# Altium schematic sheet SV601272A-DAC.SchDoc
size 431 x 279 mm; Date: Not shown in title block; ApprovedBy: Not shown in title block; CheckedBy: Not shown in title block; Author: Not shown in title block; CompanyName: Not shown in title block; Engineer: Not shown in title block; Organization: Not shown in title block; Address1: Not shown in title block; Address2: Not shown in title block; Address3: Not shown in title block; Address4: Not shown in title block; DocumentNumber: 8; Revision: Use project parameter SCH_Rev; SheetNumber: 8; SheetTotal: 11; PageSetup: Record=PageOptions¦CenterHorizontal=True¦CenterVertical=True¦PrintScale=1.00¦XCorrection=1.00¦YCorrection=1.00¦PrintKind=0¦BorderSize=5000000¦LeftOffset=0¦BottomOffset=0¦Orientation=2¦PaperLength=1000¦PaperWidth=1000¦Scale=100¦PaperSource=15¦PrintQuality=600¦MediaType=1¦DitherType=10¦PaperKind=Letter¦PrintScaleMode=1
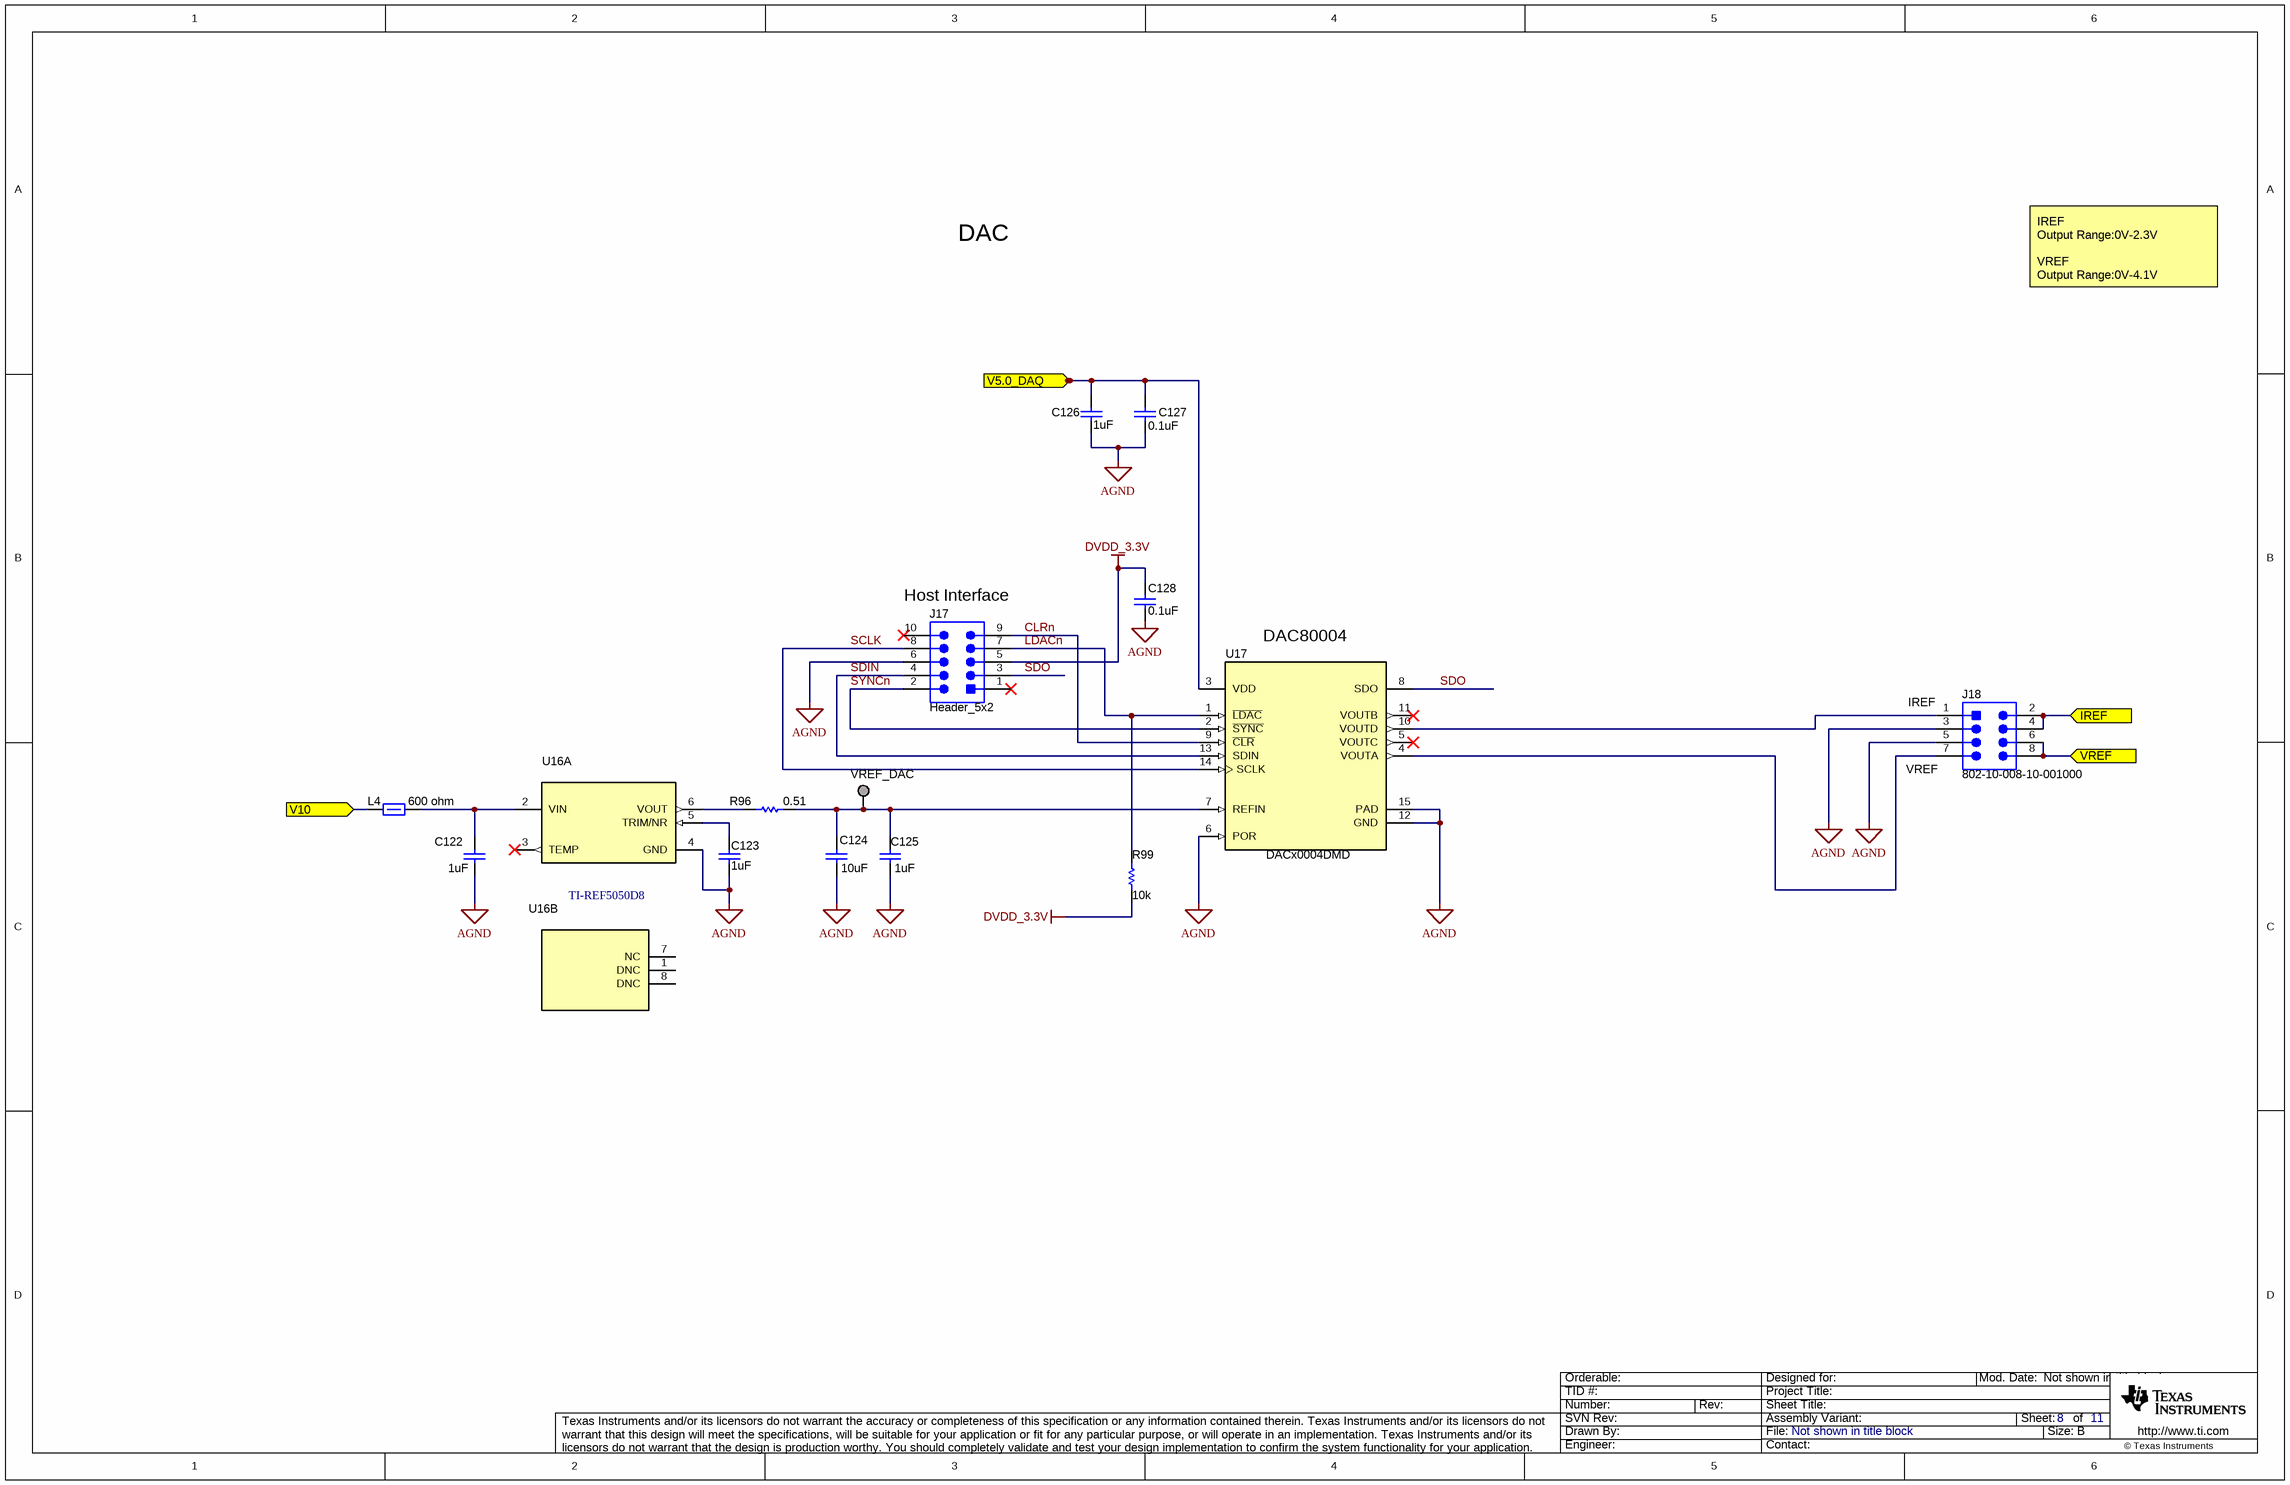
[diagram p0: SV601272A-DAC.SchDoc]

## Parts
C122  ValueDisplayed: 1uF  [1206]  (hidden comment: Capacitor)
C123  ValueDisplayed: 1uF  [1206]  (hidden comment: Capacitor)
C124  ValueDisplayed: 10uF  [0805_HV]  (hidden comment: Capacitor)
C125  ValueDisplayed: 1uF  [1206]  (hidden comment: Capacitor)
C126  ValueDisplayed: 1uF  [1206]  (hidden comment: Capacitor)
C127  ValueDisplayed: 0.1uF  [0603]  (hidden comment: Capacitor)
C128  ValueDisplayed: 0.1uF  [0603]  (hidden comment: Capacitor)
J17  Header_5x2  [Assman_AWHW-10G-0x02-T]
J18  802-10-008-10-001000  [Mill-Max_802-10-008-10-001000]
L4  value 600 ohm  [0603]  (hidden comment: Ferrite_Bead)
R96  ValueDisplayed: 0.51  [0603]  (hidden comment: Resistor)
R99  ValueDisplayed: 10k  [0603]  (hidden comment: Resistor)
U16  TI-REF5050D8  [D0008A_N]  (parts A,B of 2)
U17  DACx0004DMD  [DMD0014A]
VREF_DAC  Pogo Pad  [PogoPad]  (value not drawn)  (no BOM)

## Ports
IREF, V5.0_DAQ, V10, VREF

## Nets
AGND: C122.2 C123.2 C124.2 C125.2 C126.2 C127.2 C128.2 J17.6 J18.3 J18.5 U16.4(GND) U17.6(POR) U17.12(GND) U17.15(PAD)
DVDD_3.3V: C128.1 J17.5 R99.1
CLRn: J17.9 U17.9(~{CLR})
IREF: J18.2 J18.4 ; port IREF
LDACn: J17.7 R99.2 U17.1(~{LDAC})
SCLK: J17.8 U17.14(SCLK)
SDIN: J17.4 U17.13(SDIN)
SDO: J17.3 U17.8(SDO)
SYNCn: J17.2 U17.2(~{SYNC})
V5.0_DAQ: C126.1 C127.1 U17.3(VDD) ; port V5.0_DAQ
V10: L4.1 ; port V10
VREF: J18.6 J18.8 ; port VREF
NetC122_1: C122.1 L4.2 U16.2(VIN)
NetC123_1: C123.1 U16.5(TRIM/NR)
NetC124_1: C124.1 C125.1 R96.2 U17.7(REFIN) VREF_DAC.1
NetJ18_1: J18.1 U17.10(VOUTD)
NetJ18_7: J18.7 U17.4(VOUTA)
NetR96_1: R96.1 U16.6(VOUT)

Not connected (* = marked no-connect by the designer): J17 1* 10*; U16 1(DNC) 3(TEMP)* 7(NC) 8(DNC); U17 5(VOUTC)* 11(VOUTB)*

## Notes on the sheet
- DAC
- IREF
  Output Range:0V-2.3V
  VREF
  Output Range:0V-4.1V
- (near J17) Host Interface
- (near U17) DAC80004
- (near J18) IREF
- (near J18) VREF

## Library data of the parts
C122 C123 C125 C126 = CMP-0008509-2: CAP, CERM, 1 uF, 25 V, +/- 10%, X7R, 1206; PartNumber: 12063C105KAT2A; Manufacturer: AVX; Polarized: N; Value: 1uF; U/M: EA; Cap_F: 1µF; ESR_ohm: 0.013; Value1: 0.013 ohm; VDC_V: 25V; TaMin_C: -55°C; TaMax_C: 125°C; SizeArea_mm2: 5.12; SizeAreaWB_mm2: 10.92; SizeX_mm: 3.2; SizeY_mm: 1.6; SizeZ_mm: 1.35; AEC Category: Q200
C124 = CMP-0008273-1: CAP, CERM, 10 uF, 35 V, +/- 10%, X6S, 0805; PartNumber: GRM21BC8YA106KE11L; Manufacturer: MuRata; Polarized: N; Value: 10uF; U/M: EA; Cap_F: 10µF; Value1: Unknown; VDC_V: 35V; TaMin_C: -55°C; TaMax_C: 105°C; Cap_Case: 0805; SizeArea_mm2: 2.5; SizeAreaWB_mm2: 6.75; SizeX_mm: 2; SizeY_mm: 1.25; SizeZ_mm: 1.45; AEC Category: Q200
C127 C128 = CMP-0006857-4: CAP, CERM, 0.1 uF, 16 V, +/- 5%, X7R, 0603; PartNumber: C0603C104J4RACTU; Manufacturer: Kemet; Polarized: N; Value: 0.1uF; U/M: EA; Cap_F: 100nF; Value1: Unknown; VDC_V: 16V; TaMin_C: -55°C; TaMax_C: 125°C; SizeArea_mm2: 1.28; SizeAreaWB_mm2: 4.68; SizeX_mm: 1.6; SizeY_mm: 0.8; SizeZ_mm: 1; AEC Category: Q200
J17 = CMP-0075161-1: Header(Shrouded), 2.54mm, 5x2, Gold, TH; PartNumber: AWHW-10G-0202-T; Manufacturer: Assman WSW; Pitch_mm: 2.54; Gender: Male; Shrouded: Y; Row_Count: 2; CNHeader: False; Green_Lifecycle: Active; Green_REACh: Passed
J18 = CMP-0055096-1: Header, 2.54 mm, 4x2, Gold, TH; Manufacturer: Mill-Max; CNHeader: TRUE; Shrouded: N; Gender: Male; Row_Count: 2; RowSpacing_mm: 2.54; CT: FALSE
L4 = CMP-0003197-2: Ferrite Bead, 600 ohm @ 100 MHz, 1 A, 0603; PartNumber: 742792651; Manufacturer: Wurth Elektronik; Imax_A: 1A; DCR_ohm: 2d; Value1: 0.2 ohm; ZTyp@100MHz_Ohm: 600; Ztyp@1GHz_Ohm: 257.548; SizeArea_mm2: 1.28; SizeAreaWB_mm2: 4.68; SizeX_mm: 1.6; SizeY_mm: 0.8; SizeZ_mm: 1
R96 = CMP-0022717-2: RES, 0.51, 1%, 0.1 W, AEC-Q200 Grade 1, 0603; PartNumber: ERJ-3RQFR51V; Manufacturer: Panasonic; Value: 0.51; Res_ohm: 5.1d; Value_Code: R510; Power_W: 100mW; Value2: 0.1W; TempCo: 300 ppm/C; SizeArea_mm2: 1.28; SizeX_mm: 1.6; SizeY_mm: 0.8; SizeZ_mm: 1; EIA_Code: E96; U/M: EA; AEC Category: Q200; AEC Qualified: Y
R99 = CMP-0025701-4: RES, 10 k, 5%, 0.1 W, AEC-Q200 Grade 0, 0603; PartNumber: CRCW060310K0JNEA; Manufacturer: Vishay-Dale; Value: 10k; Value_Code: 10k0; Power_W: 100mW; Value2: 0.1W; VDC_V: 75V; TempCo: 200 ppm/C; SizeArea_mm2: 1.28; SizeX_mm: 1.6; SizeY_mm: 0.8; SizeZ_mm: 1; EIA_Code: E24; AEC Category: Q200; AEC Qualified: Y; AEC Grade: 0
U16 = CMP-0032617-1: Low Noise, Very Low Drift, Precision Voltage Reference, -40 to 125 degC, 8-pin SOIC (D), Green (RoHS & no Sb/Br); PartNumber: REF5050AID; Manufacturer: Texas Instruments; Initial Accuracy @ 25/deg C(%): 0.05; Iout/Iz(Max)(mA): 10; Iq(Max)(uA): 1000; Rating: Catalog; SubFamily: Series Voltage Reference; Temp Coeff(Max)(ppm/ degree C): 3; VI(Max)(V): 18; VI(Min)(V): 5.2; VO(V): 5
U17 = CMP-0013342-2: QUAD 16-BIT, 1LSB INL, BUFFERED, VOLTAGE-OUTPUT DIGITAL-to-ANALOG CONVERTERS, DMD0014A (VSON-14); PartNumber: DAC80004IDMD; Manufacturer: Texas Instruments; SizeArea_mm2: 12; SizeAreaWB_mm2: 20; SizeX_mm: 3; SizeY_mm: 4; SizeZ_mm: 1; CompType: IC; U/M: EA
VREF_DAC = PogoPad: Pad for Pogo Pin Connector; SymbolCreator: codlsc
